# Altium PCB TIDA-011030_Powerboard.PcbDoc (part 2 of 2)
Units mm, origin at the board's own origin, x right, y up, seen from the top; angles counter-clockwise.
Board outline 86.79 x 21.79 mm, 4 copper layers (Top Layer, Mid Layer 1, Mid Layer 2, Bottom Layer), stack 1.57 mm thick; 19 components, 12 nets, 39 pads, 602 vias.
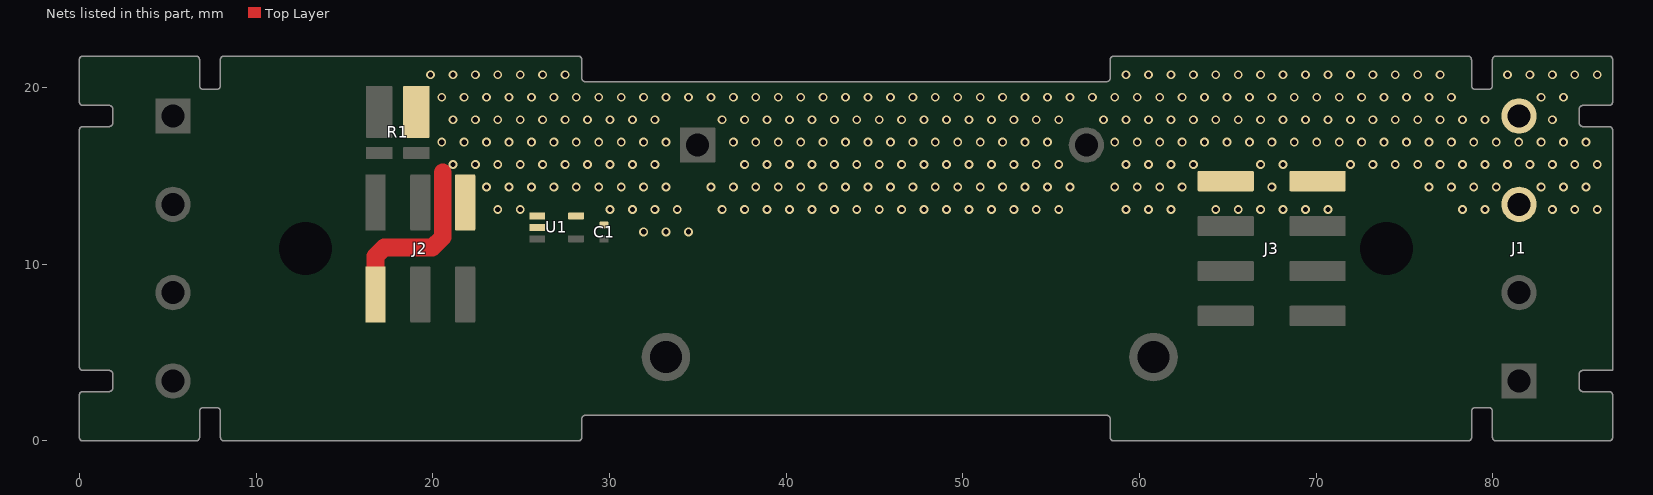
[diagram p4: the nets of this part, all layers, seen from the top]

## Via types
v1: diameter 0.5, hole 0.3, Top Layer to Bottom Layer, tented both sides, 602 vias

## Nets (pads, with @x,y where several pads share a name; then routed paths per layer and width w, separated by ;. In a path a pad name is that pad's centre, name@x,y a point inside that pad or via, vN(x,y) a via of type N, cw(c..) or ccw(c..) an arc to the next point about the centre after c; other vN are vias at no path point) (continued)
Neutral: C1.1 J1.3 J1.4 J2.1 J2.6 J3.1 J3.2 R1.3 U1.1 U1.2 U1.5 | length 10.1
  Top Layer w0.381: 16.76,10.46 16.803,10.503
  Top Layer w1: J2.1@16.76,8.293 16.76,10.46 ; 16.803,10.503 17.25,10.95 19.984,10.95 20.57,11.536 20.57,15.2
  other v1: 31.941,11.836 33.21,11.836 34.48,11.836 23.685,13.106 24.956,13.106 30.035,13.106 31.305,13.106 32.575,13.106 33.846,13.106 36.386,13.106 37.655,13.106 38.925,13.106 40.195,13.106 41.465,13.106 42.735,13.106 44.005,13.106 45.276,13.106 46.545,13.106 47.816,13.106 49.085,13.106 50.355,13.106 51.625,13.106 52.895,13.106 54.165,13.106 55.435,13.106 59.245,13.106 60.515,13.106 61.785,13.106 64.325,13.106 65.596,13.106 66.865,13.106 68.135,13.106 69.406,13.106 70.675,13.106 78.295,13.106 79.566,13.106 83.376,13.106 84.645,13.106 85.915,13.106 23.05,14.376 24.32,14.376 25.59,14.376 26.86,14.376 28.13,14.376 29.4,14.376 30.67,14.376 31.941,14.376 33.21,14.376 35.75,14.376 37.02,14.376 38.291,14.376 39.56,14.376 40.831,14.376 42.1,14.376 43.37,14.376 44.64,14.376 45.91,14.376 47.18,14.376 48.45,14.376 49.721,14.376 50.99,14.376 52.261,14.376 53.53,14.376 54.8,14.376 56.07,14.376 58.61,14.376 59.88,14.376 61.151,14.376 62.42,14.376 67.501,14.376 76.391,14.376 77.66,14.376 78.93,14.376 80.2,14.376 82.74,14.376 84.01,14.376 85.281,14.376 21.145,15.646 22.415,15.646 23.685,15.646 24.956,15.646 26.226,15.646 27.495,15.646 28.765,15.646 30.035,15.646 31.305,15.646 32.575,15.646 37.655,15.646 38.925,15.646 40.195,15.646 41.465,15.646 42.735,15.646 44.005,15.646 45.276,15.646 46.545,15.646 47.816,15.646 49.085,15.646 50.355,15.646 51.625,15.646 52.895,15.646 54.165,15.646 55.435,15.646 59.245,15.646 60.515,15.646 61.785,15.646 63.055,15.646 66.865,15.646 68.135,15.646 71.945,15.646 73.215,15.646 74.486,15.646 75.755,15.646 77.025,15.646 78.295,15.646 79.566,15.646 80.835,15.646 82.105,15.646 83.376,15.646 84.645,15.646 85.915,15.646 20.511,16.916 21.78,16.916 23.05,16.916 24.32,16.916 25.59,16.916 26.86,16.916 28.13,16.916 29.4,16.916 30.67,16.916 31.941,16.916 33.21,16.916 37.02,16.916 38.291,16.916 39.56,16.916 40.831,16.916 42.1,16.916 43.37,16.916 44.64,16.916 45.91,16.916 47.18,16.916 48.45,16.916 49.721,16.916 50.99,16.916 52.261,16.916 53.53,16.916 54.8,16.916 58.61,16.916 59.88,16.916 61.151,16.916 62.42,16.916 63.691,16.916 64.96,16.916 66.23,16.916 67.501,16.916 68.77,16.916 70.04,16.916 71.31,16.916 72.581,16.916 73.85,16.916 75.12,16.916 76.391,16.916 77.66,16.916 78.93,16.916 80.2,16.916 81.471,16.916 82.74,16.916 84.01,16.916 85.281,16.916 21.145,18.186 22.415,18.186 23.685,18.186 24.956,18.186 26.226,18.186 27.495,18.186 28.765,18.186 30.035,18.186 31.305,18.186 32.575,18.186 36.386,18.186 37.655,18.186 38.925,18.186 40.195,18.186 41.465,18.186 42.735,18.186 44.005,18.186 45.276,18.186 46.545,18.186 47.816,18.186 49.085,18.186 50.355,18.186 51.625,18.186 52.895,18.186 54.165,18.186 55.435,18.186 57.975,18.186 59.245,18.186 60.515,18.186 61.785,18.186 63.055,18.186 64.325,18.186 65.596,18.186 66.865,18.186 68.135,18.186 69.406,18.186 70.675,18.186 71.945,18.186 73.215,18.186 74.486,18.186 75.755,18.186 77.025,18.186 78.295,18.186 79.566,18.186 83.376,18.186 20.511,19.456 21.78,19.456 23.05,19.456 24.32,19.456 25.59,19.456 26.86,19.456 28.13,19.456 29.4,19.456 30.67,19.456 31.941,19.456 33.21,19.456 34.48,19.456 35.75,19.456 37.02,19.456 38.291,19.456 39.56,19.456 40.831,19.456 42.1,19.456 43.37,19.456 44.64,19.456 45.91,19.456 47.18,19.456 48.45,19.456 49.721,19.456 50.99,19.456 52.261,19.456 53.53,19.456 54.8,19.456 56.07,19.456 57.34,19.456 58.61,19.456 59.88,19.456 61.151,19.456 62.42,19.456 63.691,19.456 64.96,19.456 66.23,19.456 67.501,19.456 68.77,19.456 70.04,19.456 71.31,19.456 72.581,19.456 73.85,19.456 75.12,19.456 76.391,19.456 77.66,19.456 82.74,19.456 84.01,19.456 19.875,20.726 21.145,20.726 22.415,20.726 23.685,20.726 24.956,20.726 26.226,20.726 27.495,20.726 59.245,20.726 60.515,20.726 61.785,20.726 63.055,20.726 64.325,20.726 65.596,20.726 66.865,20.726 68.135,20.726 69.406,20.726 70.675,20.726 71.945,20.726 73.215,20.726 74.486,20.726 75.755,20.726 77.025,20.726 80.835,20.726 82.105,20.726 83.376,20.726 84.645,20.726 85.915,20.726
pads on no net: J3.5 J3.6

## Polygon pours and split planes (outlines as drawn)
NetJ4_3 on Top Layer "TOP_LAYER_NETJ4_3_P104" (solid, remove dead copper, pour order 104): 35.5,9.2 28.7,9.2 28.2,8.7 24.318,8.7 24.271,8.652 12.798,8.652 11.55,9.9 0.026,9.9 0,0 35.5,0
NetJ4_1 on Top Layer "TOP_LAYER_NETJ4_1_P116" (solid, remove dead copper, pour order 116): 16.022,16.575 16.016,13.666 15.745,13.395 12.554,13.395 12.554,11.971 12.625,11.9 9.991,11.9 -0.035,11.9 0.001,21.8 17.721,21.8 17.721,16.575
Neutral on Top Layer "TOP_LAYER_NEUTRAL_P112" (solid, remove dead copper, pour order 112): 20.069,15.9 20.069,15.055 20.3,14.4 20.3,11.9 21.84,11.9 23,11.9 31.3,11.9 31.9,11.3 61.6,11.3 63.7,13.4 74.1,13.4 75.6,11.9 86.764,11.9 86.8,21.7 86.7,21.8 18.331,21.8 18.331,15.9
Line on Top Layer "TOP_LAYER_LINE_P109" (solid, remove dead copper, pour order 109): 86.79,9.86 75.21,9.86 73.75,8.4 58.75,8.4 58.75,0 86.79,0
NetJ4_1 on Mid Layer 1 "MID_LAYER_1_NETJ4_1_P103" (solid, remove dead copper, pour order 103): 17.4,21.8 0.001,21.8 -0.02,11.901 9.992,11.901 17.02,11.901 17.4,12.281 17.4,19.4
Neutral on Mid Layer 1 "MID_LAYER_1_NEUTRAL_P113" (solid, remove dead copper, pour order 113): 18.554,11.921 19.12,11.355 73.555,11.355 74.066,11.866 74.934,11.866 86.754,11.866 86.754,21.905 86.654,22.005 18.554,22.005
Line on Mid Layer 1 "MID_LAYER_1_LINE_P111" (solid, remove dead copper, pour order 111): 74.775,9.85 73.8,8.875 58.75,8.875 58.75,0 86.79,0 86.79,6.3 86.79,9.85
NetJ4_3 on Mid Layer 1 "MID_LAYER_1_NETJ4_3_P107" (solid, remove dead copper, pour order 107): 35.5,9.35 14.751,9.35 12.9,9.35 12.342,9.908 -0.027,9.908 0.001,0 35.5,0
NetJ4_1 on Mid Layer 2 "MID_LAYER_2_NETJ4_1_P115" (solid, remove dead copper, pour order 115): 17.4,21.8 0.001,21.8 0,11.926 10.017,11.926 17.044,11.926 17.4,12.283 17.4,19.4
Neutral on Mid Layer 2 "MID_LAYER_2_NEUTRAL_P114" (solid, remove dead copper, pour order 114): 19.1,11.375 73.25,11.375 73.75,11.875 86.8,11.875 86.8,21.7 86.7,21.8 18.6,21.8 18.6,11.875
Line on Mid Layer 2 "MID_LAYER_2_LINE_P100" (solid, remove dead copper, pour order 100): 73.475,8.875 58.75,8.875 58.75,0 86.789,0 86.79,9.86 74.46,9.86
NetJ4_3 on Mid Layer 2 "MID_LAYER_2_NETJ4_3_P106" (solid, remove dead copper, pour order 106): 35.5,9.35 14.828,9.35 13.2,9.35 12.642,9.908 0,9.908 0,0 35.5,0
NetJ4_1 on Bottom Layer "BOTTOM_LAYER_NETJ4_1_P117" (solid, remove dead copper, pour order 117): 17.4,13.725 17.4,11.925 -0.001,11.925 0.001,15.4 0.001,21.8 17.4,21.8 17.4,19.4 17.4,14.9
Line on Bottom Layer "BOTTOM_LAYER_LINE_P110" (solid, remove dead copper, pour order 110): 70.809,8.875 58.75,8.875 58.75,0 86.789,0 86.789,9.9 75.1,9.9 74.075,8.875
Neutral on Bottom Layer "BOTTOM_LAYER_NEUTRAL_P102" (solid, remove dead copper, pour order 102): 19.1,11.375 73,11.375 73.5,11.875 78.235,11.875 86.764,11.875 86.8,21.7 86.7,21.8 18.6,21.8 18.6,11.875
NetJ4_3 on Bottom Layer "BOTTOM_LAYER_NETJ4_3_P105" (solid, remove dead copper, pour order 105): 35.5,9.35 16.511,9.35 12.64,9.35 12.086,9.905 0,9.905 0,0 35.5,0

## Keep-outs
Keep-Out Layer:
  text ".Layer_Name" at 14.656,-21.806 h1.52

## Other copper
Top Layer:
  text ".Layer_Name" at 14.656,-21.806 h1.52
Bottom Layer:
  text ".Layer_Name" at 14.656,-21.806 h1.52

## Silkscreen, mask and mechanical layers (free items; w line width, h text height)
Top Overlay:
  text "N" at 74.425,18.077 h0.76
  text "N" at 11.852,18.027 h0.76
  text "L" at 11.852,3.156 h0.76
  text "<<< Load <<<" at 15.577,3.156 h0.76
  text "<<< Input <<<" at 62.827,3.156 h0.76
  text "L" at 74.427,3.156 h0.76
  text "DANGER HIGH VOLTAGE" at 11.7,0.75 h1.52
  text "DANGER HIGH VOLTAGE" at 58.925,0.75 h1.52
  text ".Layer_Name" at 14.656,-21.806 h1.52
Bottom Overlay:
  text "DANGER HIGH VOLTAGE" at 24.3,17.225 h1.52
  text "DANGER HIGH VOLTAGE" at 78.225,17.075 h1.52
  text "TIDA-011030" at 51.665,16.252 h1.1
  text ".Layer_Name" at 14.656,-21.806 h1.52
Top Paste:
  text ".Layer_Name" at 14.656,-21.806 h1.52
Bottom Paste:
  text ".Layer_Name" at 14.656,-21.806 h1.52
Top Solder:
  text ".Layer_Name" at 14.656,-21.806 h1.52
  text ".Layer_Name" at 14.656,-21.806 h1.52
Bottom Solder:
  text ".Layer_Name" at 14.656,-21.806 h1.52
Drill Guide:
  text ".Layer_Name" at 14.656,-21.806 h1.52
M1 Board Outline:
  lines w0.2: 0,0.2 0,2.595 ; 0,2.594 cw(c0.2,2.594) 0.2,2.794 1.686,2.797 ccw(c1.686,2.997) 1.886,2.997 ; 0,4.195 0,17.595 ; 0,17.594 cw(c0.2,17.594) 0.2,17.794 ; 0,19.195 0,21.59 ; 0,21.589 cw(c0.2,21.589) 0.2,21.789 ; 0.001,0.2 ccw(c0.201,0.2) 0.201,0 ; 0.001,4.195 ccw(c0.201,4.195) 0.201,3.995 ; 0.001,19.195 ccw(c0.201,19.195) 0.201,18.995 ; 0.2,0 6.604,0.001 ccw(c6.604,0.201) 6.804,0.201 ; 0.2,3.995 1.686,3.995 cw(c1.686,3.795) 1.886,3.795 1.886,2.995 ; 0.2,17.795 1.686,17.797 ccw(c1.686,17.997) 1.886,17.997 ; 0.2,18.995 1.686,18.995 cw(c1.686,18.795) 1.886,18.795 1.886,17.995 ; 0.2,21.79 6.604,21.79 cw(c6.604,21.59) 6.804,21.59 6.804,20.104 ; 6.804,0.2 6.804,1.686 ; 6.804,1.685 cw(c7.004,1.685) 7.004,1.885 7.786,1.886 ; 6.805,20.104 ccw(c7.005,20.104) 7.005,19.904 ; 7.004,19.904 7.786,19.904 ; 7.785,1.886 cw(c7.785,1.686) 7.985,1.686 7.988,0.2 ccw(c8.188,0.2) 8.188,0 ; 7.786,19.905 ccw(c7.786,20.105) 7.986,20.105 ; 7.986,20.104 7.986,21.59 ; 7.986,21.589 cw(c8.186,21.589) 8.186,21.789 28.239,21.79 cw(c28.239,21.59) 28.439,21.59 28.439,20.54 ; 8.186,0 28.239,0 ccw(c28.239,0.2) 28.439,0.2 28.439,1.25 cw(c28.639,1.25) 28.639,1.45 58.151,1.45 ; 28.44,20.54 ccw(c28.64,20.54) 28.64,20.34 ; 28.639,20.34 58.151,20.34 ; 58.15,1.45 cw(c58.15,1.25) 58.35,1.25 58.353,0.2 ccw(c58.553,0.2) 58.553,0 ; 58.151,20.342 ccw(c58.151,20.542) 58.351,20.542 ; 58.351,20.54 58.351,21.59 ; 58.351,21.589 cw(c58.551,21.589) 58.551,21.789 78.595,21.79 ; 58.551,0 78.604,0 ccw(c78.604,0.2) 78.804,0.2 78.804,1.686 cw(c79.004,1.686) 79.004,1.886 79.787,1.886 cw(c79.787,1.686) 79.987,1.686 79.988,0.2 ccw(c80.188,0.2) 80.188,0 ; 78.594,21.79 cw(c78.594,21.59) 78.794,21.59 ; 78.804,20.104 78.804,21.59 ; 78.805,20.104 ccw(c79.005,20.104) 79.005,19.904 ; 79.004,19.904 79.786,19.904 ; 79.786,19.905 ccw(c79.786,20.105) 79.986,20.105 ; 79.986,20.104 79.986,21.59 ; 79.986,21.589 cw(c80.186,21.589) 80.186,21.789 ; 80.186,0 86.59,0.001 ccw(c86.59,0.201) 86.79,0.201 ; 80.186,21.79 86.59,21.79 ; 84.904,17.995 84.904,18.795 ; 84.904,18.794 cw(c85.104,18.794) 85.104,18.994 ; 84.905,17.995 ccw(c85.105,17.995) 85.105,17.795 ; 85.104,2.795 86.59,2.795 ; 85.104,17.795 86.59,17.795 ; 85.104,18.995 86.59,18.995 ; 85.105,2.795 cw(c85.105,2.995) 84.905,2.995 84.904,3.795 cw(c85.104,3.795) 85.104,3.995 86.79,3.995 86.79,17.595 ; 86.589,2.795 cw(c86.589,2.595) 86.789,2.595 ; 86.589,17.795 cw(c86.589,17.595) 86.789,17.595 ; 86.589,21.79 cw(c86.589,21.59) 86.789,21.59 ; 86.59,18.997 ccw(c86.59,19.197) 86.79,19.197 ; 86.79,0.2 86.79,2.595 ; 86.79,19.195 86.79,21.59
  text ".Layer_Name" at 14.656,-21.806 h1.52
M2 Board Dimensions:
  rectangle: 3.175,-10.16 12.7,-6.985
  rectangle: 0,-6.985 3.175,-3.81
  lines w0.178: 0,-6.985 25.4,-6.985 ; 3.175,-10.16 3.175,-3.81 ; 6.35,-10.16 6.35,-3.81 ; 12.7,-10.16 12.7,-3.81 ; 19.05,-10.16 19.05,-3.81 ; 0,-10.16 0,-3.81 25.4,-3.81 25.4,-10.16 0,-10.16
  text ".Layer_Name" at 14.656,-21.806 h1.52
M3 3D STEP Top:
  drawing of 1866 lines, arcs and shapes, not listed
  text ".Layer_Name" at 14.656,-21.806 h1.52
M4 3D STEP Bottom:
  text ".Layer_Name" at 14.656,-21.806 h1.52
M5 Assembly Top:
  lines w0.254: -7.417,-23.626 160.223,-23.626 ; -7.417,-18.462 160.274,-18.462 ; -7.417,-13.297 -7.417,-28.791 94.31,-28.791 160.274,-28.791 160.274,-13.297 -7.404,-13.297 -7.404,-28.791 32.614,-28.791 ; 55.194,-28.791 55.194,-13.297 ; 87.376,-18.462 87.376,-13.297 ; 108.712,-18.462 108.712,-13.297 ; 124.511,-28.956 124.511,-23.804
  text "COMPONENTS MARKED 'DNP' SHOULD NOT BE POPULATED." at 29.299,-8.09 h1.52
  text "ASSEMBLY VARIANT:" at 29.286,-11.024 h1.52
  text ".VariantName" at 55.601,-11.024 h1.52
  text "PCB VIEWED FROM TOP SIDE" at -5.804,-16.654 h1.52
  text "BOARD #:" at 57.099,-16.654 h1.52
  text ".PRJ_Number" at 70.955,-16.654 h1.52
  text "REV:" at 92.405,-16.654 h1.52
  text ".PCB_Rev" at 99.809,-16.654 h1.52
  text "SVN REV:" at 113.69,-16.654 h1.52
  text ".VersionControl_RevNumber" at 126.543,-16.654 h1.52
  text "PLOT NAME =" at -5.804,-27.034 h1.52
  text ".plot_File_Name" at 14.656,-27.034 h1.52
  text "GENERATED    :" at 57.15,-27.034 h1.52
  text ".Print_Date" at 79.235,-27.034 h1.52
  text ".Print_Time" at 97.752,-27.034 h1.52
  text "TEXAS INSTRUMENTS" at 129.87,-27.034 h1.52
M6 Assembly Bottom:
  lines w0.254: -7.429,-18.474 160.261,-18.474 ; -7.379,-23.639 160.261,-23.639 ; 28.334,-28.969 28.334,-23.817 ; 44.133,-18.474 44.133,-13.31 ; 65.468,-18.474 65.468,-13.31 ; 97.65,-28.804 97.65,-13.31 ; 120.231,-28.804 160.249,-28.804 160.249,-13.31 -7.429,-13.31 -7.429,-28.804 58.534,-28.804 160.261,-28.804 160.261,-13.31
  text "COMPONENTS MARKED 'DNP' SHOULD NOT BE POPULATED." at 154.991,-8.077 h1.52
  text ".VariantName" at 128.473,-11.024 h1.52
  text "ASSEMBLY VARIANT:" at 154.864,-11.024 h1.52
  text ".VersionControl_RevNumber" at 26.302,-16.667 h1.52
  text "SVN REV:" at 39.154,-16.667 h1.52
  text ".PCB_Rev" at 53.035,-16.667 h1.52
  text "REV:" at 60.439,-16.667 h1.52
  text ".PRJ_Number" at 81.89,-16.667 h1.52
  text "BOARD #:" at 95.745,-16.667 h1.52
  text "PCB VIEWED FROM BOTTOM SIDE" at 158.648,-16.667 h1.52
  text "TEXAS INSTRUMENTS" at 22.974,-27.047 h1.52
  text ".Print_Time" at 55.093,-27.047 h1.52
  text ".Print_Date" at 73.609,-27.047 h1.52
  text "GENERATED    :" at 95.694,-27.047 h1.52
  text ".plot_File_Name" at 138.189,-27.047 h1.52
  text "PLOT NAME =" at 158.648,-27.047 h1.52
M9 Title Sheet:
  drawing of 63 lines, arcs and shapes, not listed
  text "1" at 35.293,466.75 h1.78
  text "2" at 136.766,466.75 h1.78
  text "3" at 238.239,466.75 h1.78
  text "4" at 339.865,466.75 h1.78
  text "5" at 441.423,466.75 h1.78
  text "6" at 542.98,466.75 h1.78
  text "7" at 644.623,466.75 h1.78
  text "8" at 746.096,466.75 h1.78
  text "A" at -11.874,405.841 h1.78
  text "A" at 793.305,405.841 h1.78
  text "B" at -11.874,278.841 h1.78
  text "B" at 793.305,278.841 h1.78
  text "C" at -11.874,151.841 h1.78
  text "C" at 793.305,151.841 h1.78
  text "D" at -11.874,24.841 h1.78
  text "D" at 793.305,24.841 h1.78
  text "PROJECT TITLE:" at 714.947,6.823 h1.14
  text ".PRJ_Title" at 716.216,3.436 h1.78
  text "DESIGNED FOR:" at 714.947,-0.823 h1.14
  text ".PRJ_Customer" at 716.216,-4.379 h1.78
  text "FILE NAME:" at 714.947,-8.443 h1.14
  text ".PCB_File_Name_No_Path" at 716.216,-11.491 h1.78
  text "Texas Instruments (TI) and/or its licensors do not warrant the accuracy or completeness of this specification" at 588.721,-15.601 h1.14
  text "ENGINEER:" at 714.947,-15.809 h1.14
  text "LAYOUT BY:" at 753.173,-15.809 h1.14
  text "or any information contained therein. TI and/or its licensors do not warrant that this design will meet" at 587.579,-18.463 h1.14
  text ".PRJ_Engineer" at 716.216,-19.746 h1.78
  text ".PCB_Layout" at 754.456,-19.746 h1.78
  text "the specifications, will be suitable for your application or fit for any particular purpose, or will operate in" at 587.579,-21.325 h1.14
  text ".Layer_Name" at 14.656,-21.806 h1.52
  text "ALTIUM DESIGNER VERSION:" at 753.173,-23.683 h1.14
  text "an implementation. TI and/or its licensors do not warrant that the design is production worthy. You should" at 587.579,-24.187 h1.14
  text "completely validate and test your design implementation to confirm the system functionality for your application." at 588.721,-27.048 h1.14
  text ".print_Scale" at 716.216,-27.069 h1.78
  text ".Application_BuildNumber" at 754.456,-27.069 h1.78
  text "1" at 35.293,-33.503 h1.78
  text "2" at 136.766,-33.503 h1.78
  text "3" at 238.239,-33.503 h1.78
  text "4" at 339.865,-33.503 h1.78
  text "5" at 441.423,-33.503 h1.78
  text "6" at 542.98,-33.503 h1.78
  text "7" at 644.623,-33.503 h1.78
  text "8" at 746.096,-33.503 h1.78
M10 Fab Notes:
  drawing of 189 lines, arcs and shapes, not listed
  text "DESIGN INFORMATION" at 741.376,161.675 h1.52
  text "MIN. TRACK WIDTH:" at 725.004,158.319 h1.52
  text "8" at 752.848,158.32 h1.52
  text "MIL" at 756.779,158.319 h1.52
  text "MIN. CLEARANCE:" at 725.004,155.167 h1.52
  text "7.874" at 748.5,155.167 h1.52
  text "MIL" at 756.779,155.167 h1.52
  text "MIN. VIA PAD SIZE:" at 725.004,152.014 h1.52
  text "24" at 752.087,152.014 h1.52
  text "MIL" at 756.779,152.014 h1.52
  text "0.05mm (2MIL)" at 742.657,148.714 h1.52
  text "MINIMUM ANNULAR RING" at 716.641,148.506 h1.52
  text "EXTERNAL" at 760.64,148.506 h1.52
  text "PER" at 721.721,145.708 h1.52
  text "IPC-D-275 CLASS 2 LEVEL C" at 727.309,145.708 h1.52
  text "MIL, HOLES" at 765.11,143.156 h1.52
  text "+/-" at 755.142,142.938 h1.52
  text "+/-" at 776.834,142.938 h1.52
  text "REGISTRATION TOLERANCES:" at 716.641,142.911 h1.52
  text "METAL" at 747.116,142.911 h1.52
  text "5" at 761.751,142.911 h1.52
  text "3" at 782.909,142.911 h1.52
  text "MIL" at 785.862,142.911 h1.52
  text "HOLE SIZE TOLERANCE (UNLESS OTHERWISE SPECIFIED):" at 716.641,140.414 h1.52
  text "+/-" at 776.834,140.341 h1.52
  text "3" at 782.909,140.314 h1.52
  text "MIL" at 785.862,140.314 h1.52
  text "MATERIAL:" at 714.742,136.818 h1.52
  text "FR-4 High Tg" at 739.798,133.553 h1.52
  text "X" at 736.129,133.35 h1.52
  text "FR-4" at 725.436,133.235 h1.52
  text "OTHER" at 763.231,133.235 h1.52
  text "62 MIL (1.6mm) +/-10%" at 733.566,129.602 h1.52
  text "X" at 730.516,129.54 h1.52
  text "THICKNESS:" at 716.641,129.394 h1.52
  text "OTHER" at 766.203,129.394 h1.52
  text "TOLERANCE:" at 716.641,125.88 h1.52
  text "X" at 738.187,125.88 h1.52
  text "ANSI IPC-6012 TYPE 3 CLASS 2" at 742.708,125.88 h1.52
  text "OTHER +/-" at 742.708,122.218 h1.52
  text "BOW & TWIST:" at 716.641,118.53 h1.52
  text "X" at 738.187,118.53 h1.52
  text "ANSI IPC-6012 TYPE 3 CLASS 2" at 742.708,118.53 h1.52
  text "OTHER +/-" at 742.708,114.804 h1.52
  text "DRILLING:" at 714.742,111.486 h1.52
  text "NC_DRILL FILES" at 759.472,108.815 h1.52
  text "REFERENCE:" at 716.641,108.715 h1.52
  text "X" at 733.335,108.712 h1.52
  text "AS SHOWN" at 737.856,108.715 h1.52
  text "X" at 756.221,108.715 h1.52
  text "OTHER" at 767.041,105.101 h1.52
  text "PTH COPPER THICKNESS:" at 716.633,105.012 h1.52
  text "X" at 745.57,105.012 h1.52
  text "20-30 um" at 748.821,105.012 h1.52
  text "BOARD FINISH:" at 714.742,101.263 h1.52
  text "SILKSCREEN:" at 718.685,98.466 h1.52
  text "X" at 743.013,98.466 h1.52
  text "TOP" at 745.984,98.466 h1.52
  text "X" at 755.967,98.466 h1.52
  text "BOTTOM" at 758.964,98.466 h1.52
  text "SILKSCREEN COLOR:" at 718.685,94.524 h1.52
  text "X" at 742.987,94.524 h1.52
  text "WHITE" at 745.984,94.524 h1.52
  text "OTHER" at 758.964,94.524 h1.52
  text "X" at 746.315,90.88 h1.52
  text "GREEN" at 749.312,90.88 h1.52
  text "OTHER" at 765.009,90.88 h1.52
  text "SOLDER RESIST COLOR:" at 718.685,90.706 h1.52
  text "X" at 746.315,86.962 h1.52
  text "MATTE" at 749.312,86.962 h1.52
  text "SEMI-GLOSS" at 764.997,86.946 h1.52
  text "IMMERSION GOLD (ENIG)" at 741.692,82.574 h1.52
  text "ENEPIG" at 775.665,82.39 h1.52
  text "SURFACE FINISH:" at 714.742,82.365 h1.52
  text "X" at 737.171,82.365 h1.52
  text "IMM. TIN/SILVER OR EQUIV" at 723.113,78.877 h1.52
  text "OTHER" at 759.472,78.777 h1.52
  text "ARRAY/PANEL:" at 714.742,74.831 h1.52
  text "CUT AND TRIM PER M1 BOARD OUTLINE" at 741.692,74.622 h1.52
  text "N.C. ROUTE" at 741.692,71.168 h1.52
  text "X" at 759.167,71.168 h1.52
  text "V. SCORE" at 763.688,71.168 h1.52
  text "CERTIFICATION:" at 714.742,67.888 h1.52
  text "MATERIALS AND WORKMANSHIP FOR ALL PCBS" at 733.157,67.888 h1.52
  text "TO MEET OR EXCEED THE REQUIREMENTS OF:" at 733.157,65.499 h1.52
  text "X" at 723.95,62.232 h1.52
  text "ANSI IPC-A-600F CLASS ->" at 727.201,62.232 h1.52
  text "X" at 769.06,62.232 h1.52
  text "2" at 771.854,62.232 h1.52
  text "1" at 763.853,62.194 h1.52
  text "3" at 780.846,62.194 h1.52
  text "X" at 744.575,58.481 h1.52
  text "RoHS" at 747.826,58.481 h1.52
  text "OTHER" at 764.194,58.481 h1.52
  text "PER ORDER" at 774.279,58.481 h1.52
  text "ALL BOARDS MUST MEET OR EXCEED UL94-V0 REQUIREMENTS." at 715.442,54.574 h1.52
  text "PCB MUST BEAR THE UL94V-0 UL REGISTERED MATERIAL ID NUMBER" at 715.442,51.626 h1.52
  text "ADDITIONAL REQUIREMENTS:" at 714.742,47.322 h1.52
  text "MICROSECTION:" at 716.641,44.601 h1.52
  text "YES" at 739.647,44.601 h1.52
  text "REQUIRED" at 761.529,40.935 h1.52
  text "BARE BOARD ELEC. TEST:" at 716.641,40.863 h1.52
  text "NONE" at 749.807,40.863 h1.52
  text "X" at 758.532,40.863 h1.52
  text "PER ORDER" at 776.566,40.863 h1.52
  text "XX MIL VIAS REQUIRE NON-CONDUCTIVE FILL AND PLANARIZE" at 720.912,35.657 h1.5
  text "XX MIL VIAS REQUIRE CONDUCTIVE FILL AND PLANARIZE" at 721.116,33.016 h1.52
  text "OUTER XX MIL TRACES REQUIRE 50 OHM SINGLE-ENDED IMPEDANCE" at 721.091,28.866 h1.47
  text "LAYER 2 & 3 (INNER LAYERS) XX MIL WIDE, XX MIL SPACE / TRACES REQUIRE 100 OHM DIFFERENTIAL IMPEDANCE" at 720.887,22.879 h1.52
  text ".Layer_Name" at 14.656,-21.806 h1.52
M11 Gerber Information:
  lines w0.254: -7.417,-23.626 160.223,-23.626 ; -7.417,-18.462 160.274,-18.462 ; -7.417,-13.297 -7.417,-28.791 94.31,-28.791 160.274,-28.791 160.274,-13.297 -7.404,-13.297 -7.404,-28.791 32.614,-28.791 ; 55.194,-28.791 55.194,-13.297 ; 87.376,-18.462 87.376,-13.297 ; 108.712,-18.462 108.712,-13.297 ; 124.511,-28.956 124.511,-23.804
  text "ALL ARTWORK VIEWED FROM TOP SIDE" at -5.804,-16.654 h1.52
  text "BOARD #:" at 57.099,-16.654 h1.52
  text ".PRJ_Number" at 70.955,-16.654 h1.52
  text "REV:" at 92.405,-16.654 h1.52
  text ".PCB_Rev" at 99.809,-16.654 h1.52
  text "SVN REV:" at 113.69,-16.654 h1.52
  text ".VersionControl_RevNumber" at 126.543,-16.654 h1.52
  text "LAYER NAME =" at -5.804,-21.806 h1.52
  text "PLOT NAME =" at -5.804,-27.034 h1.52
  text ".plot_File_Name" at 14.656,-27.034 h1.52
  text "GENERATED    :" at 57.15,-27.034 h1.52
  text ".Print_Date" at 79.235,-27.034 h1.52
  text ".Print_Time" at 97.752,-27.034 h1.52
  text "TEXAS INSTRUMENTS" at 129.87,-27.034 h1.52
M12 Stackup:
  drawing of 295 lines, arcs and shapes, not listed
  text "Layer" at 674.469,457.523 h1.52
  text "Name" at 684.88,457.523 h1.52
  text "Material" at 708.496,457.523 h1.52
  text "Thickness" at 730.334,457.523 h1.52
  text "Constant" at 746.84,457.523 h1.52
  text "Board Layer Stack" at 761.314,457.523 h1.52
  text "Top Overlay" at 684.88,454.475 h1.52
  text "Top Solder" at 684.88,451.427 h1.52
  text "Solder Resist" at 708.496,451.427 h1.52
  text "0.50mil" at 730.334,451.427 h1.52
  text "3.8" at 746.84,451.427 h1.52
  text "1" at 674.469,448.379 h1.52
  text "Top Layer" at 684.88,448.379 h1.52
  text "1.38mil" at 730.334,448.379 h1.52
  text "Dielectric 1" at 684.88,445.331 h1.52
  text "2313" at 708.496,445.331 h1.52
  text "3.94mil" at 730.334,445.331 h1.52
  text "4.05" at 746.84,445.331 h1.52
  text "2" at 674.469,442.283 h1.52
  text "Mid Layer 1" at 684.88,442.283 h1.52
  text "0.69mil" at 730.334,442.283 h1.52
  text "Core" at 684.88,439.235 h1.52
  text "FR-4" at 708.496,439.235 h1.52
  text "49.80mil" at 730.334,439.235 h1.52
  text "4.5" at 746.84,439.235 h1.52
  text "3" at 674.469,436.187 h1.52
  text "Mid Layer 2" at 684.88,436.187 h1.52
  text "0.69mil" at 730.334,436.187 h1.52
  text "Dielectric 2" at 684.88,433.139 h1.52
  text "2313" at 708.496,433.139 h1.52
  text "3.94mil" at 730.334,433.139 h1.52
  text "4.05" at 746.84,433.139 h1.52
  text "4" at 674.469,430.091 h1.52
  text "Bottom Layer" at 684.88,430.091 h1.52
  text "1.38mil" at 730.334,430.091 h1.52
  text "Bottom Solder" at 684.88,427.043 h1.52
  text "Solder Resist" at 708.496,427.043 h1.52
  text "0.50mil" at 730.334,427.043 h1.52
  text "3.8" at 746.84,427.043 h1.52
  text "Bottom Overlay" at 684.88,423.995 h1.52
  text ".Layer_Name" at 14.656,-21.806 h1.52
M13 Component Bodies Top:
  text ".Layer_Name" at 14.656,-21.806 h1.52
M14 Component Bodies Bottom:
  text ".Layer_Name" at 14.656,-21.806 h1.52
M15 Courtyards Top:
  text ".Layer_Name" at 14.656,-21.806 h1.52
M16 Courtyards Bottom:
  text ".Layer_Name" at 14.656,-21.806 h1.52
Drill Drawing:
  circle w0.254: c93.641,8.349 r0.702
  lines w0.254: 92.939,4.84 93.29,4.84 93.641,4.489 93.991,4.84 94.342,4.84 93.991,5.191 94.342,5.542 93.991,5.542 93.641,5.892 93.29,5.542 92.939,5.542 93.29,5.191 92.939,4.84 ; 92.939,10.805 94.342,10.805 94.342,12.208 92.939,12.208 92.939,10.805 ; 92.939,15.366 94.342,15.366 93.641,13.962 92.939,15.366
  lines w0.305: 91.667,3.542 173.746,3.542 ; 91.667,16.173 173.746,16.173 ; 100.248,0.384 100.248,19.33 ; 108.681,0.384 108.681,19.33 ; 124.85,0.384 124.85,19.33 ; 131.432,0.384 131.432,19.33 ; 140.961,0.384 140.961,19.33 ; 159.359,0.384 159.359,19.33 ; 91.667,0.384 173.746,0.384 173.746,19.33 91.667,19.33 91.667,0.384
  text "Symbol" at 93.561,17.12 h1.83
  text "Quantity" at 101.196,17.12 h1.83
  text "Finished Hole Size" at 109.628,17.12 h1.83
  text "Plated" at 125.797,17.12 h1.83
  text "Hole Type" at 132.379,17.12 h1.83
  text "Drill Layer Pair" at 141.908,17.12 h1.83
  text "Hole Tolerance" at 160.306,17.12 h1.83
  text "2" at 101.196,13.962 h1.52
  text "118.11mil (3.000mm)" at 109.628,13.962 h1.52
  text "NPTH" at 125.797,13.962 h1.52
  text "Round" at 132.379,13.962 h1.52
  text "Top Layer - Bottom Layer" at 141.908,13.962 h1.52
  text "602" at 101.196,10.805 h1.52
  text "11.81mil (0.300mm)" at 109.628,10.805 h1.52
  text "PTH" at 125.797,10.805 h1.52
  text "Round" at 132.379,10.805 h1.52
  text "Top Layer - Bottom Layer" at 141.908,10.805 h1.52
  text "10" at 101.196,7.647 h1.52
  text "51.18mil (1.300mm)" at 109.628,7.647 h1.52
  text "PTH" at 125.797,7.647 h1.52
  text "Round" at 132.379,7.647 h1.52
  text "Top Layer - Bottom Layer" at 141.908,7.647 h1.52
  text "2" at 101.196,4.489 h1.52
  text "70.87mil (1.800mm)" at 109.628,4.489 h1.52
  text "PTH" at 125.797,4.489 h1.52
  text "Round" at 132.379,4.489 h1.52
  text "Top Layer - Bottom Layer" at 141.908,4.489 h1.52
  text "616 Total" at 101.196,1.331 h1.52
  text ".Layer_Name" at 14.656,-21.806 h1.52
M17 Embedded Cavity:
  text ".Layer_Name" at 14.656,-21.806 h1.52
M18 Embedded Assembly:
  text ".Layer_Name" at 14.656,-21.806 h1.52
M19 Embedded Keepout:
  text ".Layer_Name" at 14.91,-21.552 h1.52

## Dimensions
0,-10.16 to 25.4,-10.16 on M2 Board Dimensions
0,0 to 0.2,21.79 on M2 Board Dimensions
0,0 to 86.79,0.2 on M2 Board Dimensions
